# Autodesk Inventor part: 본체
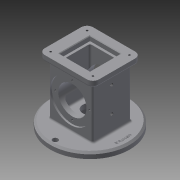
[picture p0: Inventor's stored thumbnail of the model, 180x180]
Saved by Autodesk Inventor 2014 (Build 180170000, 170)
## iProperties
Created: 2019-08
Part Number: 본체
Material: 일반
Document SubType Name: Modeling
Designer: NET
Density: 1 g/cm^3
Appearance: 기본값
Author: NET
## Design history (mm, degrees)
sketch "스케치1"
  geometry: C1 r 67.5 at (0, 0); 1 further point
  constraints: 1 centre point, 1 coincident
  dimensions: "d0" = 135 diameter of C1
extrude "돌출1" new body sketch "스케치1" distance "d1" = 10; taper "d2" = 0 deg
chamfer "모따기1" distance "d3" = 3; stored, may be unused: second distance "d4" = 2, angle "d5" = 45 deg
sketch "스케치2"
  geometry: L1 (-37, 33)-(37, 33); L2 (37, 33)-(37, -33); L3 (37, -33)-(-37, -33); L4 (-37, -33)-(-37, 33); L5 (0, 0)-(28.125, 0); L6 (0, 0)-(0, 30); C1 r 64.5 at (0, 0) reference
  constraints: 12 end point, 3 perpendicular, 2 parallel, 1 horizontal
  dimensions: "d6" = 74 distance between parallel lines of L2 L4; "d7" = 66 distance between parallel lines of L3 L1; "d8" = 37 distance between parallel lines of L4 L6; "d9" = 33 distance between parallel lines of L5 L1
extrude "돌출2" join sketch "스케치2" distance "d10" = 88; taper "d11" = 0 deg
sketch "스케치3"
  geometry: L1 (-46, 41)-(46, 41); L2 (46, 41)-(46, -41); L3 (46, -41)-(-46, -41); L4 (-46, -41)-(-46, 41); L5 (0, 0)-(0, 5.099); L6 (0, 0)-(7.648, 0)
  constraints: 12 end point, 3 parallel, 2 perpendicular, 1 horizontal
  dimensions: "d12" = 46 distance between parallel lines of L4 L5; "d13" = 92 distance between parallel lines of L2 L4; "d14" = 41 distance between parallel lines of L6 L1; "d15" = 41 distance between parallel lines of L3 L6
extrude "돌출3" join sketch "스케치3" distance "d16" = 10; taper "d17" = 0 deg
sketch "스케치4"
  geometry: L1 (74, 0)-(0, 0) reference; L2 (0, 0)-(0, 88) reference; L3 (17.587, 44)-(37, 44); L4 (-30.5, -10)-(104.5, -10) reference; L5 (37, 0)-(37, 44); C1 r 35 at (37, 44); 1 further point
  constraints: 4 end point, 2 perpendicular, 1 centre point, 1 coincident, 1 midpoint
  dimensions: "d18" = 54 distance between parallel lines of L4 L3; "d19" = 70 diameter of C1
extrude "돌출4" cut sketch "스케치4" distance "d20" = 3; taper "d21" = 0 deg
sketch "스케치5"
  geometry: C1 r 35 at (0, 0) reference; C2 r 24 at (0, 0); 1 further point
  constraints: 1 centre point, 1 coincident
  dimensions: "d22" = 48 diameter of C2
extrude "돌출5" cut sketch "스케치5" distance "d23" = 40; taper "d24" = 0 deg
sketch "스케치6"
  geometry: L1 (0, 0)-(29, 0); L2 (0, 0)-(0, 29); L3 (0, 0)-(0, -29); L4 (0, 0)-(-29, 0); C1 r 35 at (0, 0) reference; A1 r 29 centre (0, 0) between (0, 29) and (29, 0); 1 further point
  constraints: 8 end point, 4 point on circle, 2 perpendicular, 1 centre point, 1 coincident, 1 collinear, 1 horizontal
  dimensions: "d25" = 58 diameter of A1
hole "구멍1" sketch "스케치6" at (0, 29), (-29, 0), (0, -29), (29, 0) diameter "d26" = 3.242; stored, may be unused: countersink angle "d30" = 90 deg, drill point angle "d32" = 118 deg; dims "d27" = 4, "d28" = 4, "d29" = 2, "d31" = 6
sketch "스케치7"
  geometry: L1 (-37, 33)-(37, 33) reference; L2 (0, 0)-(-59, 0); L3 (0, 0)-(0, 59); L4 (0, 0)-(0, -59); C1 r 64.5 at (0, 0) reference; C2 r 4.5 at (0, 59); C3 r 4.5 at (-59, 0); C4 r 4.5 at (0, -59); A1 r 59 centre (0, 0) between (-59, 0) and (0, 59)
  constraints: 6 end point, 4 centre point, 4 coincident, 3 point on circle, 1 collinear, 1 parallel, 1 perpendicular
  dimensions: "d33" = 118 diameter of A1; "d34" = 9 diameter of C2; "d35" = 9 diameter of C3; "d36" = 9 diameter of C4
extrude "돌출6" cut sketch "스케치7" distance "d37" = 10; taper "d38" = 0 deg
sketch "스케치8"
  geometry: L1 (-26, 26)-(26, 26); L2 (26, 26)-(26, -26); L3 (26, -26)-(-26, -26); L4 (-26, -26)-(-26, 26); L5 (0, 0)-(13.11, 0); L6 (0, 0)-(0, 8.068)
  constraints: 12 end point, 3 perpendicular, 2 parallel, 1 horizontal
  dimensions: "d39" = 52 distance of L2.end L3.end; "d40" = 52 distance of L1.end L2.end; "d41" = 26 distance between parallel lines of L5 L1; "d42" = 26 distance between parallel lines of L4 L6
extrude "돌출7" cut sketch "스케치8" distance "d43" = 8; taper "d44" = 0 deg
sketch "스케치9"
  geometry: L1 (-22, 22)-(22, 22); L2 (22, 22)-(22, -22); L3 (22, -22)-(-22, -22); L4 (-22, -22)-(-22, 22); 1 further point
  constraints: 8 end point, 2 parallel, 1 horizontal, 1 perpendicular
  dimensions: "d45" = 44 distance of L2.end L3.end; "d46" = 44 distance of L1.end L2.end; "d47" = 22 distance from line of point (0, 0) L4; "d48" = 22 distance from line of point (0, 0) L1
extrude "돌출8" cut sketch "스케치9" distance "d49" = 74; taper "d50" = 0 deg
sketch "스케치10"
  geometry: C1 r 67.5 at (0, 0) reference; C2 r 25 at (0, 0)
  constraints: 1 centre point, 1 coincident
  dimensions: "d51" = 50 diameter of C2
extrude "돌출9" cut sketch "스케치10" distance "d52" = 18; taper "d53" = 0 deg
sketch "스케치11"
  geometry: C1 r 25 at (0, 0) reference; C2 r 12.5 at (0, 0)
  constraints: 1 centre point, 1 coincident
  dimensions: "d54" = 25 diameter of C2
extrude "돌출10" cut sketch "스케치11" distance "d55" = 10; taper "d56" = 0 deg
fillet "모깎기1" dims "d57" = 10
node "작업 평면1"
sketch "스케치12"
  geometry: L1 (66, 0)-(0, 0) reference; L2 (0, 88)-(66, 88) reference; L3 (33, 88)-(33, 0); L4 (21.383, 27)-(33, 27); L5 (33, 70)-(45.968, 70); L6 (58, -10)-(8, -10) reference; C1 r 10.58 at (33, 27); C2 r 4.827 at (33, 70); 1 further point
  constraints: 6 end point, 2 centre point, 2 coincident, 2 midpoint, 2 point on line, 1 parallel, 1 perpendicular
  dimensions: "d59" = 37 distance between parallel lines of L6 L4; "d60" = 43 distance between parallel lines of L4 L5; "d61" = 9.65468 diameter of C2; "d62" = 21.16088 diameter of C1
hole "구멍2" sketch "스케치12" at (33, 70), (33, 27) diameter "d63" = 4.917; stored, may be unused: countersink angle "d67" = 90 deg, drill point angle "d69" = 118 deg; dims "d64" = 16, "d65" = 4, "d66" = 2, "d68" = 16
fillet "모깎기2" dims "d70" = 3
chamfer "모따기2" distance "d71" = 1; stored, may be unused: second distance "d72" = 2, angle "d73" = 45 deg
fillet "모깎기3" dims "d74" = 3
fillet "모깎기4" dims "d75" = 3
fillet "모깎기5" dims "d76" = 3
fillet "모깎기6" dims "d77" = 3
fillet "모깎기7" dims "d78" = 3
sketch "스케치13"
  geometry: A1 r 10 centre (-36, 31) between (-36, 41) and (-46, 31) reference; A2 r 10 centre (-36, -31) between (-46, -31) and (-36, -41) reference; A3 r 10 centre (36, -31) between (36, -41) and (46, -31) reference; A4 r 10 centre (36, 31) between (46, 31) and (36, 41) reference; 1 further point
hole "구멍3" sketch "스케치13" at (-36, 31), (-36, -31), (36, 31), (36, -31) diameter "d79" = 3.242; stored, may be unused: countersink angle "d83" = 90 deg, drill point angle "d85" = 118 deg; dims "d80" = 4, "d81" = 4, "d82" = 2, "d84" = 6
sketch "스케치14"
  geometry: C1 r 64.5 at (0, 0) reference; C2 r 4.5 at (0, 59) reference; 1 further point
  constraints: 1 coincident, 1 vertical alignment, 2 other
feature "엠보싱1" sketch "스케치14" dims "d2" = 0, "d12" = 46, "d13" = 92, "d14" = 41, "d15" = 41, "d86" = 0.5, "d87" = 0
node "솔리드1"
mirror "대칭1"
